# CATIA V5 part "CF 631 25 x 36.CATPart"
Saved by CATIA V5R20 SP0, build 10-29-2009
Part number: CF 631 25 x 36
Definition: NONE
Nomenclature: CF 631 25 x 36
Source: Unknown
Description: CF 631 25 x 36
Bounding box of the stored display mesh (mm): x -13 to 23, y -22 to 22, z -22 to 22
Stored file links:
  C:\Users\Utente\Desktop\IO LAVORO\3D X SITO CF\X SITO\CF 631\CF 631 25 x 36.CATPart
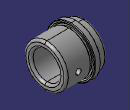
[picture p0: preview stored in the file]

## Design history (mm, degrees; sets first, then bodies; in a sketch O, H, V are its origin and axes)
Body1 "CF 631 25 x 36" (main body)
  Solid1: solid without history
